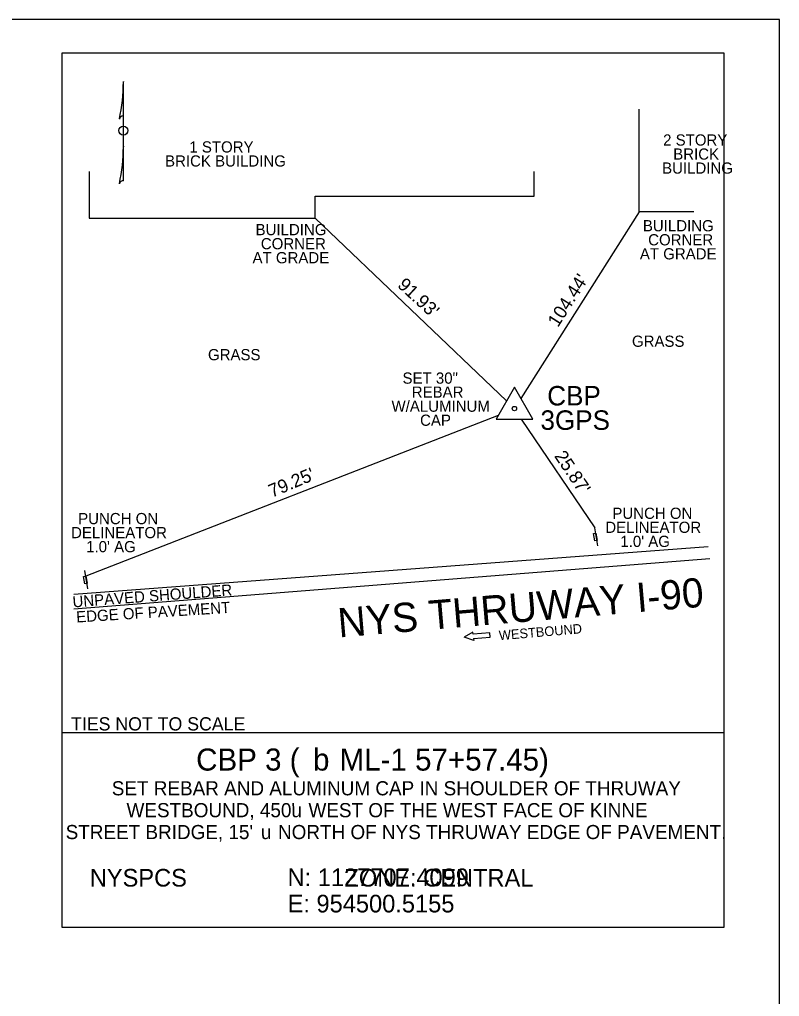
# Model space of a CAD drawing. Extents: x 953375 to 953970, y 1125154 to 1125656.
# Drawn here: x 953775 to 953970.1, y 1125404.8 to 1125655.7 of the extents above; entities that cross this region are included whole.
import ezdxf

# ---------------------------------------------------------------- set-up
doc = ezdxf.new("R2010")
doc.units = 0
for name, color, linetype in [('CB', 7, 'Continuous'), ('CBP', 7, 'Continuous'), ('CBP_C', 7, 'Continuous'), ('CBS_C', 7, 'Continuous'), ('CBT', 7, 'Continuous'), ('Default', 7, 'Continuous'), ('LUKP_C', 7, 'Continuous'), ('NNA_P', 7, 'Continuous'), ('PE', 7, 'Continuous'), ('PE_C', 7, 'Continuous'), ('PSU', 7, 'Continuous'), ('PSU_C', 7, 'Continuous'), ('RC_C', 7, 'Continuous'), ('SDEL', 7, 'Continuous')]:
    doc.layers.add(name, color=color, linetype=linetype)

# ---------------------------------------------------------------- blocks, each defined once
blk = doc.blocks.new('NNAM')
at = {"layer": 'NNA_P'}
for p, q in [((0, 0.0147), (0, 0.0501)), ((0, 0.0496), (0, 0.0496)), ((0, 0.0496), (0, 0.0496)), ((0, -0.0004), (0, 0.0147)), ((0, -0.0168), (0, -0.0004)), ((0, -0.0166), (0, -0.0168)), ((0, -0.0172), (0, -0.0168)), ((0, -0.0518), (0, -0.0172))]:
    blk.add_line(p, q, dxfattribs=at)
blk.add_circle((0, -0.0003), 0.00455, dxfattribs=at)
for centre, radius, start, end in [((-0.1834, 0.0501), 0.1834, 347.8839, 359.8678), ((0.1834, 0.0501), 0.1834, 179.9909, 180.1322), ((0, 0.0105), 0.00425, 90.435, 165.5809), ((-0.1834, -0.0164), 0.1834, 347.8839, 359.8678), ((0.1834, -0.0164), 0.1834, 179.9909, 180.1322), ((-0.1834, -0.0164), 0.1834, 359.9196, 0.009), ((0, -0.056), 0.00424, 90.0107, 164.1061)]:
    blk.add_arc(centre, radius, start, end, dxfattribs=at)

msp = doc.modelspace()

# ---------------------------------------------------------------- linework, layer by layer
at = {"layer": 'CB'}
msp.add_line((953785.84, 1125472.66), (953955.84, 1125472.66), dxfattribs=at)
msp.add_lwpolyline([(953955.84, 1125422.66), (953955.84, 1125647.11), (953785.84, 1125647.11), (953785.84, 1125422.66)], close=True, dxfattribs=at)
at = {"layer": 'CBP'}
for points in [[(953902.04, 1125561.3), (953897.32, 1125553.12)], [(953906.77, 1125553.12), (953902.04, 1125561.3)], [(953897.32, 1125553.12), (953906.77, 1125553.12)]]:
    msp.add_lwpolyline(points, dxfattribs=at)
msp.add_circle((953902.04, 1125555.84), 0.564, dxfattribs=at)
at = {"layer": 'CBT'}
for p, q in [((953897.88, 1125554.08), (953792, 1125512.83)), ((953903.75, 1125553.12), (953922.71, 1125525.23))]:
    msp.add_line(p, q, dxfattribs=at)
for points in [[(953934.06, 1125606.35), (953903.69, 1125558.44)], [(953850.86, 1125604.73), (953900.01, 1125557.78)]]:
    msp.add_lwpolyline(points, dxfattribs=at)
at = {"layer": 'Default'}
for points in [[(953374.91, 1125153.95), (953970.07, 1125153.95), (953970.07, 1125655.74), (953374.91, 1125655.74)], [(953955.84, 1125422.66), (953955.84, 1125647.11), (953785.84, 1125647.11), (953785.84, 1125422.66)]]:
    msp.add_lwpolyline(points, close=True, dxfattribs=at)
at = {"layer": 'PE'}
msp.add_line((953792.84, 1125616.73), (953792.84, 1125604.73), dxfattribs=at)
for points in [[(953934.05, 1125606.35), (953934.05, 1125632.75)], [(953792.84, 1125604.73), (953850.86, 1125604.73), (953850.86, 1125610.36), (953907.11, 1125610.36), (953907.11, 1125616.73)], [(953948.11, 1125606.35), (953934.05, 1125606.35)], [(953952.2, 1125517.25), (953788.92, 1125504.32)]]:
    msp.add_lwpolyline(points, dxfattribs=at)
at = {"layer": 'PSU'}
msp.add_lwpolyline([(953951.74, 1125520.35), (953788.92, 1125508.06)], dxfattribs=at)
at = {"layer": 'RC_C'}
for p, q in [((953891.39, 1125498.4), (953889.09, 1125497.13)), ((953891.44, 1125497.86), (953891.39, 1125498.4)), ((953895.73, 1125498.22), (953891.44, 1125497.86)), ((953895.82, 1125497.15), (953895.73, 1125498.22)), ((953891.57, 1125496.25), (953889.09, 1125497.13)), ((953891.53, 1125496.79), (953895.82, 1125497.15)), ((953891.53, 1125496.79), (953891.57, 1125496.25))]:
    msp.add_line(p, q, dxfattribs=at)
at = {"layer": 'SDEL'}
for p, q in [((953923.47, 1125520.58), (953922.71, 1125525.23)), ((953792.54, 1125509.57), (953791.78, 1125514.21))]:
    msp.add_line(p, q, dxfattribs=at)
for points in [[(953922.94, 1125523.84), (953923.24, 1125521.97), (953922.68, 1125521.87), (953922.37, 1125523.75)], [(953792, 1125512.83), (953792.31, 1125510.95), (953791.75, 1125510.86), (953791.44, 1125512.73)]]:
    msp.add_lwpolyline(points, close=True, dxfattribs=at)

# ---------------------------------------------------------------- block references
at = {"layer": 'Default', "xscale": 250, "yscale": 250}
msp.add_blockref('NNAM', (953801.64, 1125627.3), dxfattribs=at)

# ---------------------------------------------------------------- texts
at = {"layer": 'CBP_C'}
for s, height, rotation, p in [("91.93'", 3.402, 317.3376, (953871.78, 1125587.25)), ("104.44'", 3.402, 57.5254, (953913.2, 1125576.52)), ("25.87'", 3.402, 304.0201, (953912.15, 1125543.62)), ("79.25'", 3.402, 22.8967, (953839.78, 1125532.91)), ('TIES NOT TO SCALE', 3.4016, 359.9999, (953788.21, 1125473.16))]:
    msp.add_text(s, height=height, rotation=rotation, dxfattribs=at).set_placement(p)
for s, height, p in [('CBP', 5.002, (953910.46, 1125556.63)), ('3GPS', 5.002, (953908.72, 1125550.37)), ('CBP 3 (', 5.669, (953820.32, 1125462.86)), ('b', 5.67, (953850.33, 1125462.86)), (' ML-1 57+57.45)', 5.6693, (953855.04, 1125462.86)), ('SET REBAR AND ALUMINUM CAP IN SHOULDER OF THRUWAY', 3.6284, (953798.66, 1125456.5)), ("WESTBOUND, 450'", 3.6284, (953802.45, 1125450.88)), ('u', 3.63, (953844.77, 1125450.88)), (' WEST OF THE WEST FACE OF KINNE ', 3.6284, (953847.81, 1125450.88)), ("STREET BRIDGE, 15'", 3.6284, (953786.82, 1125445.26)), ('u', 3.63, (953836.95, 1125445.26)), (' NORTH OF NYS THRUWAY EDGE OF PAVEMENT.', 3.6284, (953839.99, 1125445.26)), ('N: 1127707.4099', 4.5355, (953843.8, 1125433.18)), ('NYSPCS                        ZONE: CENTRAL', 4.5355, (953793.01, 1125433.07)), ('E: 954500.5155', 4.5355, (953843.8, 1125426.43))]:
    msp.add_text(s, height=height, dxfattribs=at).set_placement(p)
at = {"layer": 'CBS_C'}
for s, p in [('2 STORY ', (953940.21, 1125623.37)), ('1 STORY ', (953818.58, 1125621.59)), ('BRICK BUILDING', (953812.34, 1125617.98)), ('BRICK ', (953942.8, 1125619.76)), ('BUILDING', (953939.95, 1125616.16)), ('BUILDING', (953935.01, 1125601.35)), ('BUILDING', (953835.58, 1125600.35)), ('CORNER', (953836.93, 1125596.74)), ('CORNER', (953936.37, 1125597.74)), ('AT GRADE', (953834.8, 1125593.14)), ('AT GRADE', (953934.24, 1125594.14)), ('SET 30" ', (953873.31, 1125562.22)), ('REBAR', (953875.68, 1125558.62)), ('W/ALUMINUM ', (953870.48, 1125555.01)), ('CAP', (953877.81, 1125551.4)), ('PUNCH ON ', (953790.03, 1125526.14)), ('PUNCH ON ', (953927.18, 1125527.5)), ('DELINEATOR', (953925.36, 1125523.9)), ('DELINEATOR', (953788.21, 1125522.54)), ("1.0' AG", (953929.23, 1125520.29)), ("1.0' AG", (953792.09, 1125518.93))]:
    msp.add_text(s, height=2.88, dxfattribs=at).set_placement(p)
at = {"layer": 'LUKP_C'}
for p in [(953932.21, 1125571.69), (953823.36, 1125568.24)]:
    msp.add_text('GRASS', height=2.88, dxfattribs=at).set_placement(p)
at = {"layer": 'PE_C'}
msp.add_text('EDGE OF PAVEMENT', height=2.88, rotation=3.6135, dxfattribs=at).set_placement((953789.62, 1125500.87))
at = {"layer": 'PSU_C'}
msp.add_text(' UNPAVED SHOULDER', height=2.88, rotation=4.3448, dxfattribs=at).set_placement((953787.63, 1125504.66))
at = {"layer": 'RC_C'}
for s, height, p in [('NYS THRUWAY I-90', 7.5024, (953857, 1125497.03)), ('WESTBOUND', 2.461, (953898.15, 1125496.33))]:
    msp.add_text(s, height=height, rotation=4.8425, dxfattribs=at).set_placement(p)

doc.saveas('drawing.dxf')
